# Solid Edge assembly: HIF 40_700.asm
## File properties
Title: Zylinder
Author: ahadarics
Template: iso assembly.asm
Last saved by: ahadarics
Revision: 76
Application: Solid Edge
Username: ahadarics
Dokumentum tartalom típus: 1
Document Number: HIF 40/700
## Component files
Kit_2.par
Kit_1.par
Profilrohr 40_700.par
Mutter.par
Kolbenstange 40_700.par
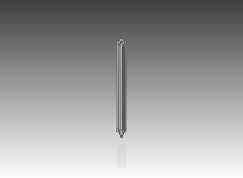
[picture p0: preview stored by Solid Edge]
